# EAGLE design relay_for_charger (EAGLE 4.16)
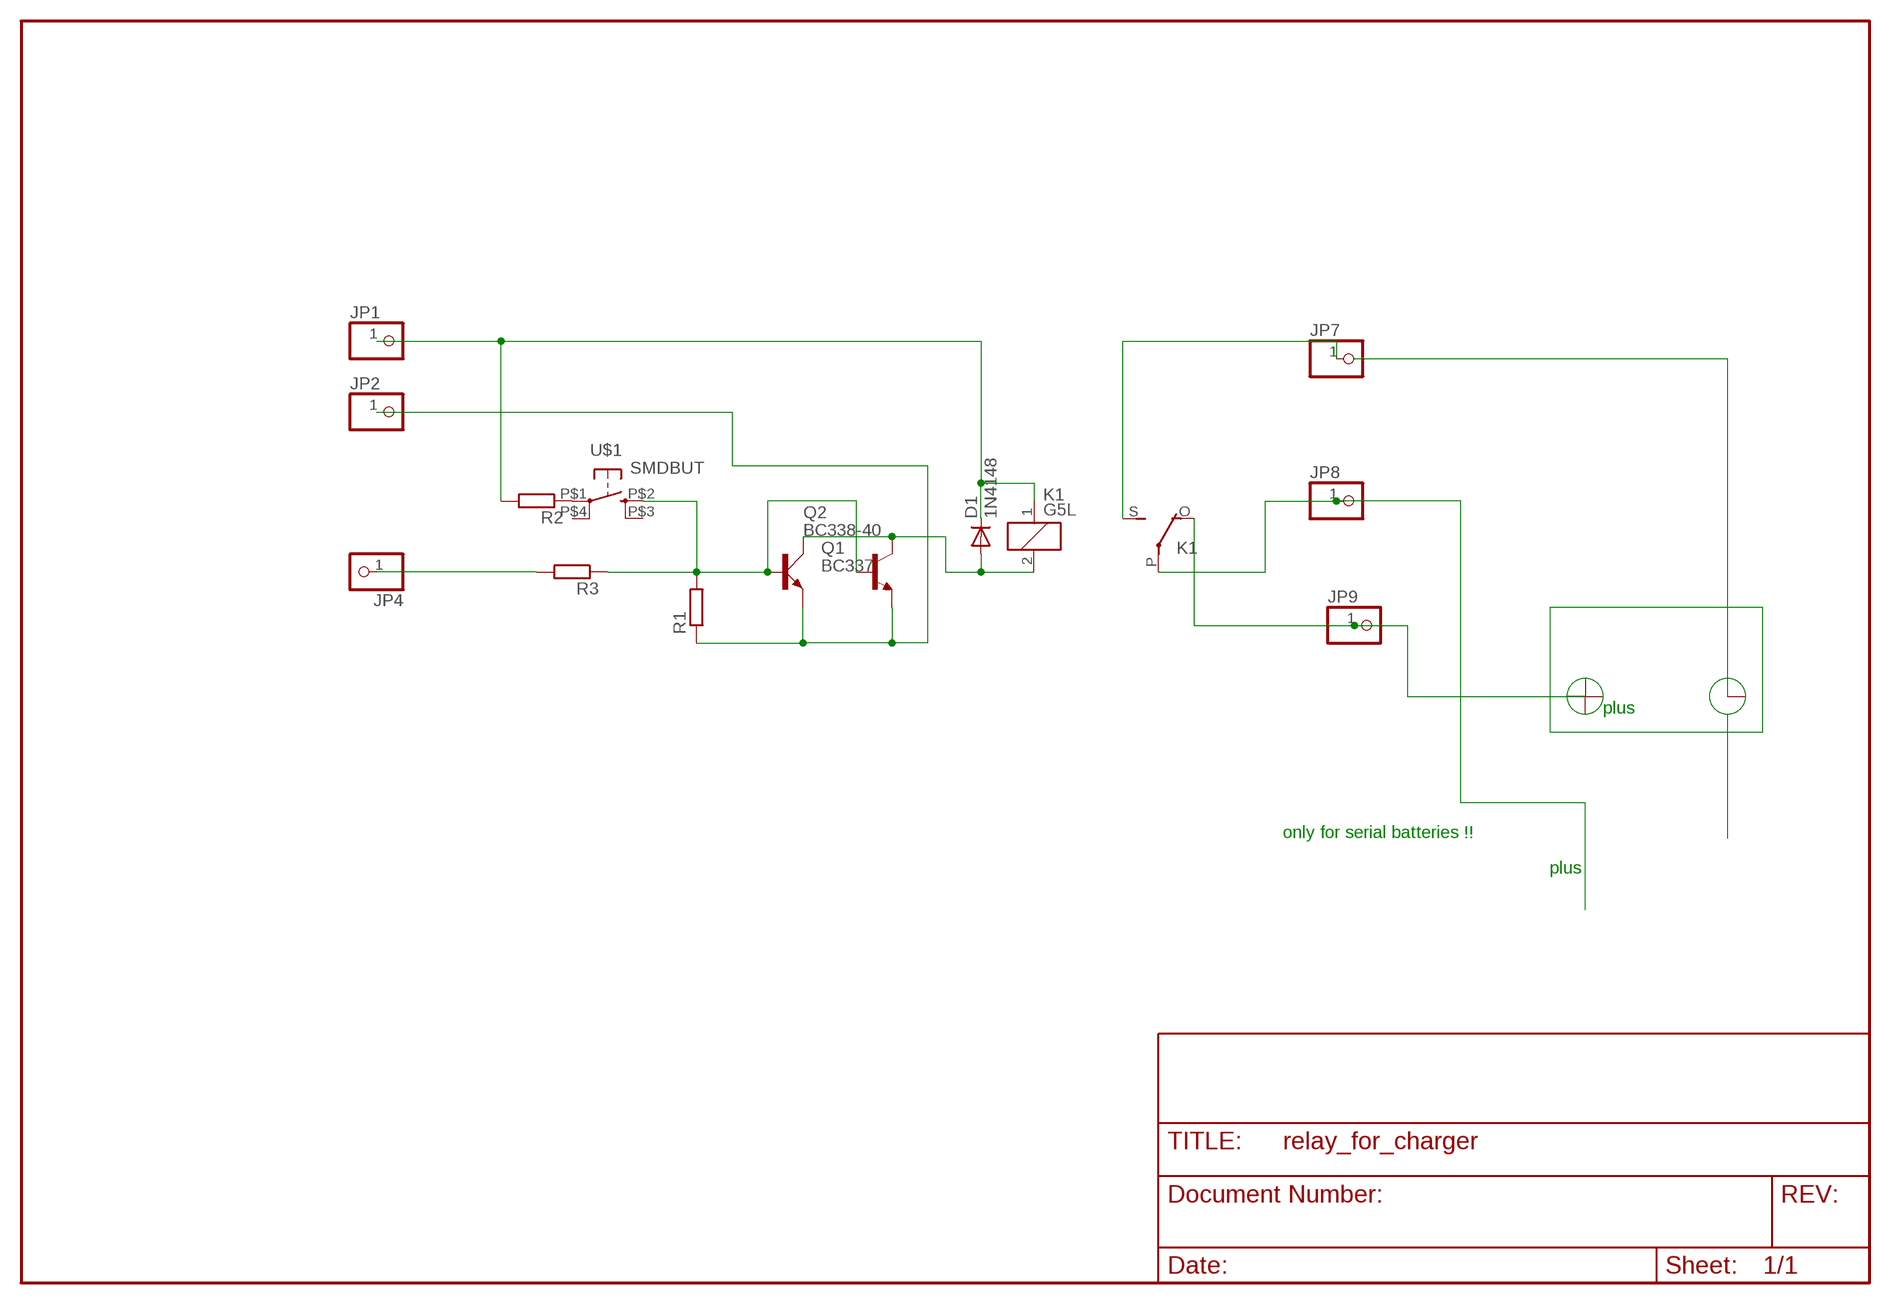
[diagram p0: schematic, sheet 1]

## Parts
D1  1N4148  [DO35-10]
JP1  PINHD-1X1M  [1X01M]
JP2  PINHD-1X1M  [1X01M]
JP4  PINHD-1X1M  [1X01M]
JP7  PINHD-1X1M  [1X01M]
JP8  PINHD-1X1M  [1X01M]
JP9  PINHD-1X1M  [1X01M]
K1  G5L  [G5LE]
Q1  BC337  [SOT54A]
Q2  BC338-40  [TO92-EBC]
R1  R-EU_0207/5V  [0207/5V]
R2  R-EU_0207/5V  [0207/5V]
R3  R-EU_0207/5V  [0207/5V]
U$1  SMDBUT  [SMD10/5]

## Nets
N$1: Q1.B Q2.B R1.2 R3.1 U$1.P$2(S)
N$2: JP2.1 Q1.E Q2.E R1.1
N$3: JP8.1 K1.P(2:P)
N$5: D1.A K1.2 Q1.C Q2.C
N$6: JP4.1 R3.2
N$7: JP9.1 K1.O(2:O)
N$8: JP7.1 K1.S(2:S)
N$9: R2.1 U$1.P$1(P)
N$10: D1.C JP1.1 K1.1 R2.2
Unconnected: U$1.P$3(S1) U$1.P$4(P1)

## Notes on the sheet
- plus
- only for serial batteries !!
- plus

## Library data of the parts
D1 = diode-1:1N4148: DIODE
JP1 JP2 JP4 JP7-JP9 = pinhead(2):PINHD-1X1: PIN HEADER
K1 = relay:G5L: RELAY 1 x switch, 10 A/120 V AC, 8 A/30 V ADC, Omron
Q1 = transistor-small-signal:BC337: NPN TRANSISTOR
Q2 = transistor-npn:BC338*: NPN Transistor
R1-R3 = rcl(2):R-EU_: RESISTOR, European symbol
U$1 = switch-omron:SMDBUT

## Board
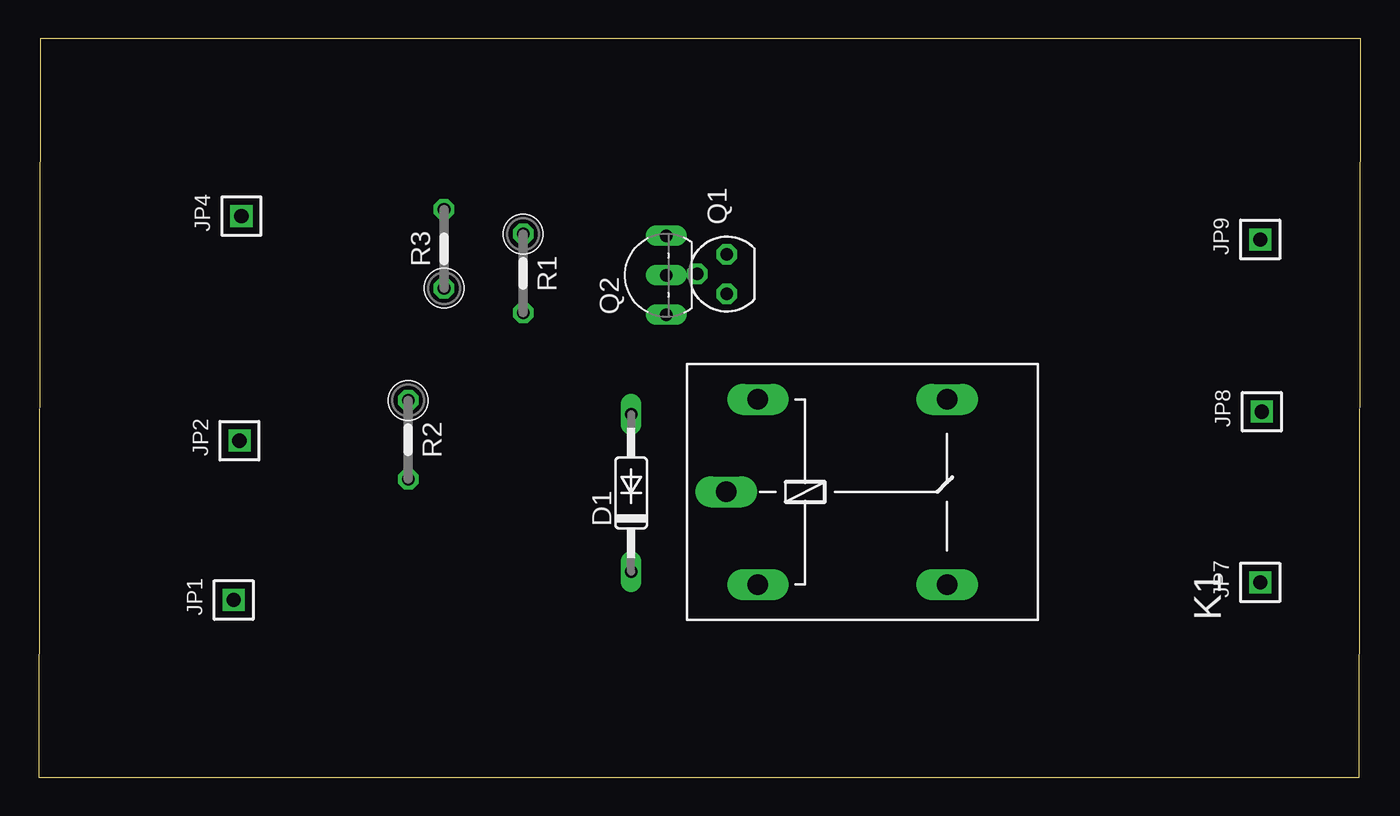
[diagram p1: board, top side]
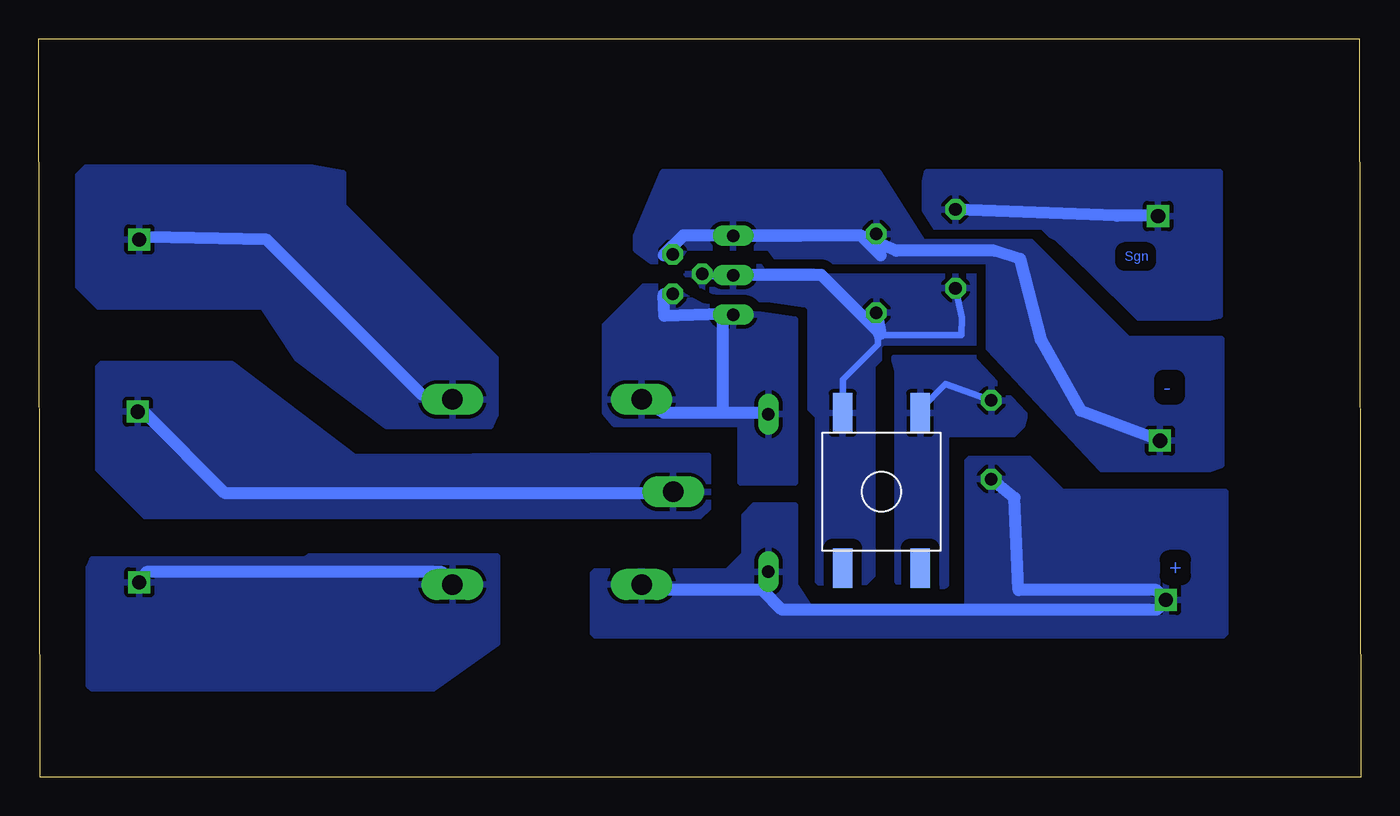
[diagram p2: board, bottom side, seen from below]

Size 85.2 x 47.6 mm. Coordinates in mm from the lower left corner, seen from the top.
Outline: 0,0 85.1,0 85.2,47.6 0.1,47.6 0,0
Copper layers (1*16): Top 0.035mm / dielectric 1.5mm / Bottom 0.035mm
Design rules "default": minimum track width 30mil, minimum drill 24mil, track to track 8mil, track to pad 8mil, pad to pad 8mil, via to via 8mil, smd to smd 8mil, copper to edge 40mil, drill to drill 8mil, minimum pad ring 10mil, minimum via ring 8mil, stop-mask expansion 4mil, vias tented up to drill 0mil, thermal gap 10mil

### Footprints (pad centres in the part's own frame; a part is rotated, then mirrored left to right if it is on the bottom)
DO35-10 = drill 0.813 long: A 5.08,0; C -5.08,0
1X01M = drill 0.914 square: 1 0,0
G5LE = drill 1.321 long: 1 -7.493,-5.969; 2 -7.493,5.969; O 4.699,5.969; P -9.525,0; S 4.699,-5.969
SOT54A = drill 0.813 octagon: B 0,1.905; C -1.27,0; E 1.27,0
TO92-EBC = drill 0.813 long: B 0,-1.27; C -2.54,-1.27; E 2.54,-1.27
0207/5V = drill 0.813 octagon: 1 -2.54,0; 2 2.54,0
SMD10/5 = smd 1.27 x 2.54: P$1 -2.5,0; P$2 2.5,0; P$3 2.5,10; P$4 -2.5,10

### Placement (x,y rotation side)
D1  38.18,18.32 90 top
JP1  12.56,11.42 0 top
JP2  12.94,21.69 0 top
JP4  13.06,36.16 0 top
JP7  78.72,12.56 0 top
JP8  78.82,23.56 0 top
JP9  78.72,34.66 0 top
K1  53.84,18.39 0 top
Q1  44.34,32.44 90 top
Q2  39.17,32.36 90 top
R1  31.22,32.48 270 top
R2  23.81,21.75 270 top
R3  26.12,34.05 90 top
U$1  30.89,23.48 180 bottom

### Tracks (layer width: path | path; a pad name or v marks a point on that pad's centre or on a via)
N$1
  Bottom 0.406: U$1.P$2 33.42,23.48 33.47,23.43 33.47,24.13 33.37,24.23 33.37,25.63 31.1,27.9 R1.2 31.15,28.44 31.22,28.5 25.72,28.5 25.71,29.64 R3.1 | 42.44,32.29 42.47,32.26 | 42.44,32.29 Q1.B | Q2.B 42.49,32.23 42.44,32.29
  Bottom 0.762: Q2.B 34.76,32.38 30.95,28.57 R1.2
  pour Bottom (isolate 0.61, rank 3): 24.72,32.26 34.09,32.26 36.72,33.01 44.22,32.63 42.72,31.5 37.09,30.13 36.34,28.63 36.59,24.88 34.97,23.25 34.97,12.63 34.09,11.76 32.72,11.76 31.47,13.01 31.47,26.5 30.09,27.88 25.47,27.88 24.97,27.38
N$2
  Bottom 0.762: 32.22,34.92 30.95,33.65 R1.1 | 32.22,34.92 34.76,34.92 Q2.E 36.03,34.92 43.65,34.92 44.92,33.65 Q1.E | 32.22,34.92 29.95,33.94 23.6,33.94 21.93,33.4 20.58,28.15 18.04,23.61 JP2.1
  pour Bottom (isolate 0.61): 8.97,28.25 14.97,28.25 21.22,34.51 28.22,34.51 31.09,39.01 44.97,39.01 46.72,34.88 46.72,34.01 45.72,33.26 44.09,33.26 43.47,34.13 38.09,34.13 37.47,33.26 23.97,33.26 23.97,27.63 16.72,19.88 9.72,19.88 8.97,20.13
N$3
  Bottom 0.762: JP8.1 78.26,23.38 73.18,18.3 45.24,18.3 K1.P
  pour Bottom (isolate 0.61, rank 2): 42.07,20.73 64.87,20.63 72.77,26.63 81.17,26.63 81.37,26.43 81.37,19.83 78.37,16.83 42.57,16.83 42.07,17.33
N$5
  Bottom 0.762: 41.11,29.84 44.88,29.73 44.92,31.11 Q1.C | 41.11,23.49 44.92,23.49 K1.2 | 41.11,23.49 38.57,23.49 D1.A | 41.11,23.49 41.11,29.84 | 41.11,29.84 Q2.C
  pour Bottom (isolate 0.61, rank 2): 44.72,31.63 46.22,31.63 48.72,29.13 48.72,23.5 48.09,22.75 39.97,22.75 39.97,19 36.47,19 36.47,29.5 42.47,30.38
N$6
  Bottom 0.762: R3.2 15.71,36.19 13.17,36.19 JP4.1
  pour Bottom (isolate 0.61, rank 3): 9.1,39.01 9.1,29.75 9.72,29.63 14.35,29.63 17.34,32.63 19.59,34.76 20.84,35.38 27.84,35.38 28.09,36.51 28.09,38.38 27.97,39.01
N$7
  Bottom 0.762: JP9.1 78.26,34.81 70.5,34.65 60.48,24.65 K1.O
  pour Bottom (rank 2): 55.77,27.03 55.77,23.33 56.07,22.63 62.77,22.63 68.57,27.03 70.77,30.33 81.37,30.33 82.67,31.63 82.67,38.8 82.17,39.3 67.57,39.3 65.57,38.93 65.57,36.83
N$8
  Bottom 0.762: JP7.1 78.26,13.22 59.21,13.22 K1.S
  pour Bottom (isolate 0.61, rank 2): 55.67,14.23 67.77,14.23 68.07,14.03 81.77,14.03 81.97,13.53 81.97,5.93 81.77,5.73 59.77,5.73 55.67,8.63
N$9
  Bottom 0.406: U$1.P$1 28.39,23.71 26.76,25.34 R2.1
  pour Bottom (isolate 0.61, rank 2): 21.09,25.38 21.47,25.38 23.09,27 30.09,27 29.84,26.25 29.84,12.63 29.47,12.01 27.34,12.01 26.72,12.38 26.72,21.88 26.59,22.13 22.34,22.13 21.84,22.63
N$10
  Bottom 0.762: 38.57,12.06 44.92,12.06 K1.1 | R2.2 22.31,18 22.06,12.06 13.17,12.06 JP1.1 13.17,10.79 37.3,10.79 38.57,12.06 | 38.57,12.06 D1.C
  pour Bottom (isolate 0.61): 8.72,18.38 19.22,18.38 21.34,20.5 25.22,20.5 25.34,20.38 25.34,11.01 25.47,10.88 35.47,10.88 36.47,12.38 36.47,17.5 39.09,17.5 39.72,16.88 39.72,14.38 40.84,13.26 49.34,13.26 49.47,13.13 49.47,9.26 49.34,9.13 8.85,9.13 8.72,9.26

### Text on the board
Bottom: Sgn | - | +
